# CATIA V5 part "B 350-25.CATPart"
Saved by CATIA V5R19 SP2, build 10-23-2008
Part number: BS 350-25
Bounding box of the stored display mesh (mm): x -15.868 to 15.868, y -15.868 to 15.868, z 0 to 100
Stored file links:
  C:\Users\Bora\Desktop\3D Katı model\B serisi\B 350\BS 350-25.CATPart
  C:\Program Files\Dassault Systemes\B19\intel_a\reffiles\standard\MetricThickPitch.txt
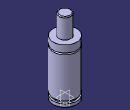
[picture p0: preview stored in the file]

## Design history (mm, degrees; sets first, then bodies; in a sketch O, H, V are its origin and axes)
Body1 (main body)
  Sketch1 on yz-plane, origin (0, 0, 0), H (0, 1, 0), V (0, 0, 1)
    point P1 (16, 63.5)
    point P4 (16, 61.5)
    point P7 (16, 63.5)
    point P8 (16, 61.5)
    point P9 (8, 99)
    point P11 (8, 99)
    line L1 (16, 63.5) -> (16, 73)
    line L2 (16, 7.5) -> (16, 61.5)
    line L3 (13.5, 7.5) -> (13.5, 4)
    arc A1 centre (16, 62.5) radius 1 from (16, 63.5) to (16, 61.5) ccw
    arc A2 centre (7, 99) radius 1 from (8, 99) to (7, 100) ccw
    line L4 (8, 99) -> (8, 73)
    line L5 (16, 0) -> (16, 4)
    line L6 (7, 100) -> (0, 100)
    point P15 (0, 100)
    line L7 (8, 73) -> (16, 73)
    line L8 (0, 0) -> (16, 0)
    line L9 (13.5, 7.5) -> (16, 7.5)
    line L10 (13.5, 4) -> (16, 4)
    coincidence: P15 V, P1 P7, P4 P8, P9 P11
    tangency: L6 A2
    horizontal: L7 H, L8 H, L9 H, L10 H
  Shaft1: profile Sketch1, axis Sketch1.V, angle 360
  Sketch2 on face of Shaft1 from Sketch1.L8, origin (0, 0, 0), H (1, 0, 0), V (0, -1, 0)
    point P1 (0, 0)
  Hole1: placed by Sketch2, at (0, 0, 0) direction (0, 0, 1), diameter 6.647, depth 7, threaded "M8", thread diameter 8, thread depth 7, pitch 1.25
